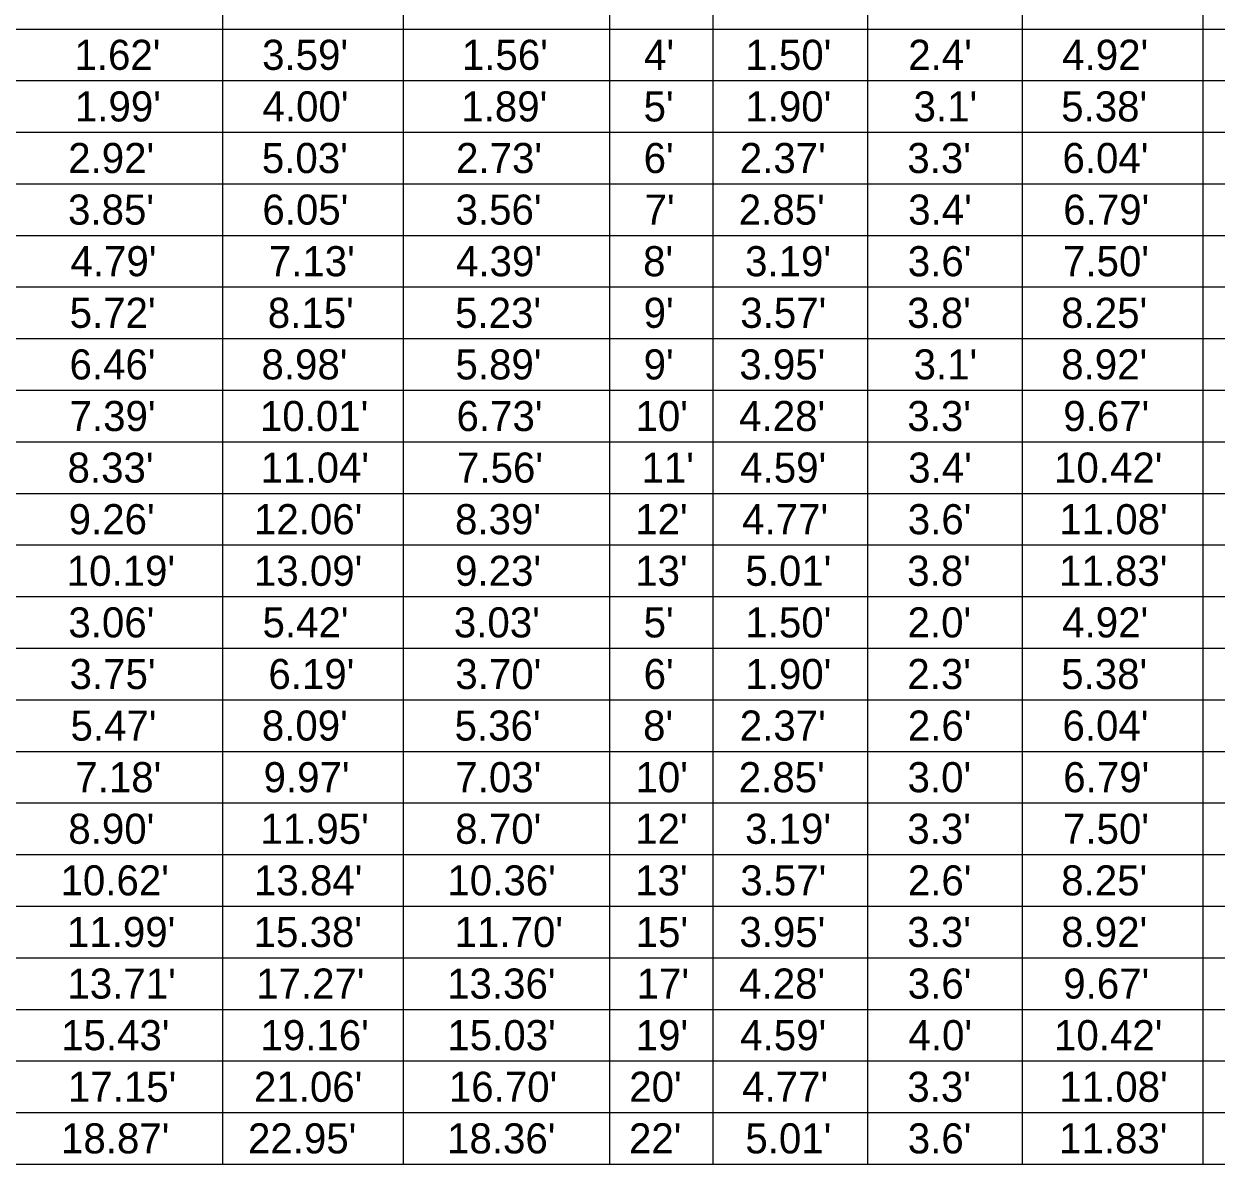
# Model space of a CAD drawing. Extents: x -1.3 to 14.6, y 0 to 8.4.
# Drawn here: x 4.058 to 6.831, y 2.19 to 4.842 of the extents above; entities that cross this region are included whole.
import ezdxf

# ---------------------------------------------------------------- set-up
doc = ezdxf.new("R2010")
doc.units = 0
doc.layers.add('Table', color=7, linetype='Continuous')

msp = doc.modelspace()

# ---------------------------------------------------------------- linework, layer by layer
at = {"layer": 'Table'}
for points in [[(4.52, 4.95), (4.52, 4.83), (4.52, 4.71), (4.52, 4.59), (4.52, 4.47), (4.52, 4.35), (4.52, 4.23), (4.52, 4.11), (4.52, 3.99), (4.52, 3.87), (4.52, 3.75), (4.52, 3.63), (4.52, 3.51), (4.52, 3.39), (4.52, 3.27), (4.52, 3.15), (4.52, 3.03), (4.52, 2.91), (4.52, 2.79), (4.52, 2.67), (4.52, 2.55), (4.52, 2.43), (4.52, 2.31), (4.52, 2.19)], [(4.94, 4.95), (4.94, 4.83), (4.94, 4.71), (4.94, 4.59), (4.94, 4.47), (4.94, 4.35), (4.94, 4.23), (4.94, 4.11), (4.94, 3.99), (4.94, 3.87), (4.94, 3.75), (4.94, 3.63), (4.94, 3.51), (4.94, 3.39), (4.94, 3.27), (4.94, 3.15), (4.94, 3.03), (4.94, 2.91), (4.94, 2.79), (4.94, 2.67), (4.94, 2.55), (4.94, 2.43), (4.94, 2.31), (4.94, 2.19)], [(5.42, 4.95), (5.42, 4.83), (5.42, 4.71), (5.42, 4.59), (5.42, 4.47), (5.42, 4.35), (5.42, 4.23), (5.42, 4.11), (5.42, 3.99), (5.42, 3.87), (5.42, 3.75), (5.42, 3.63), (5.42, 3.51), (5.42, 3.39), (5.42, 3.27), (5.42, 3.15), (5.42, 3.03), (5.42, 2.91), (5.42, 2.79), (5.42, 2.67), (5.42, 2.55), (5.42, 2.43), (5.42, 2.31), (5.42, 2.19)], [(5.66, 4.95), (5.66, 4.83), (5.66, 4.71), (5.66, 4.59), (5.66, 4.47), (5.66, 4.35), (5.66, 4.23), (5.66, 4.11), (5.66, 3.99), (5.66, 3.87), (5.66, 3.75), (5.66, 3.63), (5.66, 3.51), (5.66, 3.39), (5.66, 3.27), (5.66, 3.15), (5.66, 3.03), (5.66, 2.91), (5.66, 2.79), (5.66, 2.67), (5.66, 2.55), (5.66, 2.43), (5.66, 2.31), (5.66, 2.19)], [(6.02, 4.95), (6.02, 4.83), (6.02, 4.71), (6.02, 4.59), (6.02, 4.47), (6.02, 4.35), (6.02, 4.23), (6.02, 4.11), (6.02, 3.99), (6.02, 3.87), (6.02, 3.75), (6.02, 3.63), (6.02, 3.51), (6.02, 3.39), (6.02, 3.27), (6.02, 3.15), (6.02, 3.03), (6.02, 2.91), (6.02, 2.79), (6.02, 2.67), (6.02, 2.55), (6.02, 2.43), (6.02, 2.31), (6.02, 2.19)], [(6.38, 4.95), (6.38, 4.83), (6.38, 4.71), (6.38, 4.59), (6.38, 4.47), (6.38, 4.35), (6.38, 4.23), (6.38, 4.11), (6.38, 3.99), (6.38, 3.87), (6.38, 3.75), (6.38, 3.63), (6.38, 3.51), (6.38, 3.39), (6.38, 3.27), (6.38, 3.15), (6.38, 3.03), (6.38, 2.91), (6.38, 2.79), (6.38, 2.67), (6.38, 2.55), (6.38, 2.43), (6.38, 2.31), (6.38, 2.19)], [(6.8, 4.95), (6.8, 4.83), (6.8, 4.71), (6.8, 4.59), (6.8, 4.47), (6.8, 4.35), (6.8, 4.23), (6.8, 4.11), (6.8, 3.99), (6.8, 3.87), (6.8, 3.75), (6.8, 3.63), (6.8, 3.51), (6.8, 3.39), (6.8, 3.27), (6.8, 3.15), (6.8, 3.03), (6.8, 2.91), (6.8, 2.79), (6.8, 2.67), (6.8, 2.55), (6.8, 2.43), (6.8, 2.31), (6.8, 2.19)], [(4.04, 4.83), (4.52, 4.83), (4.94, 4.83), (5.42, 4.83), (5.66, 4.83), (6.02, 4.83), (6.38, 4.83), (6.8, 4.83), (7.22, 4.83), (7.64, 4.83), (8.06, 4.83), (8.42, 4.83), (8.84, 4.83), (9.26, 4.83), (9.68, 4.83), (10.1, 4.83), (10.52, 4.83), (10.94, 4.83), (11.36, 4.83), (11.78, 4.83), (12.2, 4.83), (12.62, 4.83), (13.04, 4.83), (13.46, 4.83)], [(4.04, 4.71), (4.52, 4.71), (4.94, 4.71), (5.42, 4.71), (5.66, 4.71), (6.02, 4.71), (6.38, 4.71), (6.8, 4.71), (7.22, 4.71), (7.64, 4.71), (8.06, 4.71), (8.42, 4.71), (8.84, 4.71), (9.26, 4.71), (9.68, 4.71), (10.1, 4.71), (10.52, 4.71), (10.94, 4.71), (11.36, 4.71), (11.78, 4.71), (12.2, 4.71), (12.62, 4.71), (13.04, 4.71), (13.46, 4.71)], [(4.04, 4.59), (4.52, 4.59), (4.94, 4.59), (5.42, 4.59), (5.66, 4.59), (6.02, 4.59), (6.38, 4.59), (6.8, 4.59), (7.22, 4.59), (7.64, 4.59), (8.06, 4.59), (8.42, 4.59), (8.84, 4.59), (9.26, 4.59), (9.68, 4.59), (10.1, 4.59), (10.52, 4.59), (10.94, 4.59), (11.36, 4.59), (11.78, 4.59), (12.2, 4.59), (12.62, 4.59), (13.04, 4.59), (13.46, 4.59)], [(4.04, 4.47), (4.52, 4.47), (4.94, 4.47), (5.42, 4.47), (5.66, 4.47), (6.02, 4.47), (6.38, 4.47), (6.8, 4.47), (7.22, 4.47), (7.64, 4.47), (8.06, 4.47), (8.42, 4.47), (8.84, 4.47), (9.26, 4.47), (9.68, 4.47), (10.1, 4.47), (10.52, 4.47), (10.94, 4.47), (11.36, 4.47), (11.78, 4.47), (12.2, 4.47), (12.62, 4.47), (13.04, 4.47), (13.46, 4.47)], [(4.04, 4.35), (4.52, 4.35), (4.94, 4.35), (5.42, 4.35), (5.66, 4.35), (6.02, 4.35), (6.38, 4.35), (6.8, 4.35), (7.22, 4.35), (7.64, 4.35), (8.06, 4.35), (8.42, 4.35), (8.84, 4.35), (9.26, 4.35), (9.68, 4.35), (10.1, 4.35), (10.52, 4.35), (10.94, 4.35), (11.36, 4.35), (11.78, 4.35), (12.2, 4.35), (12.62, 4.35), (13.04, 4.35), (13.46, 4.35)], [(4.04, 4.23), (4.52, 4.23), (4.94, 4.23), (5.42, 4.23), (5.66, 4.23), (6.02, 4.23), (6.38, 4.23), (6.8, 4.23), (7.22, 4.23), (7.64, 4.23), (8.06, 4.23), (8.42, 4.23), (8.84, 4.23), (9.26, 4.23), (9.68, 4.23), (10.1, 4.23), (10.52, 4.23), (10.94, 4.23), (11.36, 4.23), (11.78, 4.23), (12.2, 4.23), (12.62, 4.23), (13.04, 4.23), (13.46, 4.23)], [(4.04, 4.11), (4.52, 4.11), (4.94, 4.11), (5.42, 4.11), (5.66, 4.11), (6.02, 4.11), (6.38, 4.11), (6.8, 4.11), (7.22, 4.11), (7.64, 4.11), (8.06, 4.11), (8.42, 4.11), (8.84, 4.11), (9.26, 4.11), (9.68, 4.11), (10.1, 4.11), (10.52, 4.11), (10.94, 4.11), (11.36, 4.11), (11.78, 4.11), (12.2, 4.11), (12.62, 4.11), (13.04, 4.11), (13.46, 4.11)], [(4.04, 3.99), (4.52, 3.99), (4.94, 3.99), (5.42, 3.99), (5.66, 3.99), (6.02, 3.99), (6.38, 3.99), (6.8, 3.99), (7.22, 3.99), (7.64, 3.99), (8.06, 3.99), (8.42, 3.99), (8.84, 3.99), (9.26, 3.99), (9.68, 3.99), (10.1, 3.99), (10.52, 3.99), (10.94, 3.99), (11.36, 3.99), (11.78, 3.99), (12.2, 3.99), (12.62, 3.99), (13.04, 3.99), (13.46, 3.99)], [(4.04, 3.87), (4.52, 3.87), (4.94, 3.87), (5.42, 3.87), (5.66, 3.87), (6.02, 3.87), (6.38, 3.87), (6.8, 3.87), (7.22, 3.87), (7.64, 3.87), (8.06, 3.87), (8.42, 3.87), (8.84, 3.87), (9.26, 3.87), (9.68, 3.87), (10.1, 3.87), (10.52, 3.87), (10.94, 3.87), (11.36, 3.87), (11.78, 3.87), (12.2, 3.87), (12.62, 3.87), (13.04, 3.87), (13.46, 3.87)], [(4.04, 3.75), (4.52, 3.75), (4.94, 3.75), (5.42, 3.75), (5.66, 3.75), (6.02, 3.75), (6.38, 3.75), (6.8, 3.75), (7.22, 3.75), (7.64, 3.75), (8.06, 3.75), (8.42, 3.75), (8.84, 3.75), (9.26, 3.75), (9.68, 3.75), (10.1, 3.75), (10.52, 3.75), (10.94, 3.75), (11.36, 3.75), (11.78, 3.75), (12.2, 3.75), (12.62, 3.75), (13.04, 3.75), (13.46, 3.75)], [(4.04, 3.63), (4.52, 3.63), (4.94, 3.63), (5.42, 3.63), (5.66, 3.63), (6.02, 3.63), (6.38, 3.63), (6.8, 3.63), (7.22, 3.63), (7.64, 3.63), (8.06, 3.63), (8.42, 3.63), (8.84, 3.63), (9.26, 3.63), (9.68, 3.63), (10.1, 3.63), (10.52, 3.63), (10.94, 3.63), (11.36, 3.63), (11.78, 3.63), (12.2, 3.63), (12.62, 3.63), (13.04, 3.63), (13.46, 3.63)], [(4.04, 3.51), (4.52, 3.51), (4.94, 3.51), (5.42, 3.51), (5.66, 3.51), (6.02, 3.51), (6.38, 3.51), (6.8, 3.51), (7.22, 3.51), (7.64, 3.51), (8.06, 3.51), (8.42, 3.51), (8.84, 3.51), (9.26, 3.51), (9.68, 3.51), (10.1, 3.51), (10.52, 3.51), (10.94, 3.51), (11.36, 3.51), (11.78, 3.51), (12.2, 3.51), (12.62, 3.51), (13.04, 3.51), (13.46, 3.51)], [(4.04, 3.39), (4.52, 3.39), (4.94, 3.39), (5.42, 3.39), (5.66, 3.39), (6.02, 3.39), (6.38, 3.39), (6.8, 3.39), (7.22, 3.39), (7.64, 3.39), (8.06, 3.39), (8.42, 3.39), (8.84, 3.39), (9.26, 3.39), (9.68, 3.39), (10.1, 3.39), (10.52, 3.39), (10.94, 3.39), (11.36, 3.39), (11.78, 3.39), (12.2, 3.39), (12.62, 3.39), (13.04, 3.39), (13.46, 3.39)], [(4.04, 3.27), (4.52, 3.27), (4.94, 3.27), (5.42, 3.27), (5.66, 3.27), (6.02, 3.27), (6.38, 3.27), (6.8, 3.27), (7.22, 3.27), (7.64, 3.27), (8.06, 3.27), (8.42, 3.27), (8.84, 3.27), (9.26, 3.27), (9.68, 3.27), (10.1, 3.27), (10.52, 3.27), (10.94, 3.27), (11.36, 3.27), (11.78, 3.27), (12.2, 3.27), (12.62, 3.27), (13.04, 3.27), (13.46, 3.27)], [(4.04, 3.15), (4.52, 3.15), (4.94, 3.15), (5.42, 3.15), (5.66, 3.15), (6.02, 3.15), (6.38, 3.15), (6.8, 3.15), (7.22, 3.15), (7.64, 3.15), (8.06, 3.15), (8.42, 3.15), (8.84, 3.15), (9.26, 3.15), (9.68, 3.15), (10.1, 3.15), (10.52, 3.15), (10.94, 3.15), (11.36, 3.15), (11.78, 3.15), (12.2, 3.15), (12.62, 3.15), (13.04, 3.15), (13.46, 3.15)], [(4.04, 3.03), (4.52, 3.03), (4.94, 3.03), (5.42, 3.03), (5.66, 3.03), (6.02, 3.03), (6.38, 3.03), (6.8, 3.03), (7.22, 3.03), (7.64, 3.03), (8.06, 3.03), (8.42, 3.03), (8.84, 3.03), (9.26, 3.03), (9.68, 3.03), (10.1, 3.03), (10.52, 3.03), (10.94, 3.03), (11.36, 3.03), (11.78, 3.03), (12.2, 3.03), (12.62, 3.03), (13.04, 3.03), (13.46, 3.03)], [(4.04, 2.91), (4.52, 2.91), (4.94, 2.91), (5.42, 2.91), (5.66, 2.91), (6.02, 2.91), (6.38, 2.91), (6.8, 2.91), (7.22, 2.91), (7.64, 2.91), (8.06, 2.91), (8.42, 2.91), (8.84, 2.91), (9.26, 2.91), (9.68, 2.91), (10.1, 2.91), (10.52, 2.91), (10.94, 2.91), (11.36, 2.91), (11.78, 2.91), (12.2, 2.91), (12.62, 2.91), (13.04, 2.91), (13.46, 2.91)], [(4.04, 2.79), (4.52, 2.79), (4.94, 2.79), (5.42, 2.79), (5.66, 2.79), (6.02, 2.79), (6.38, 2.79), (6.8, 2.79), (7.22, 2.79), (7.64, 2.79), (8.06, 2.79), (8.42, 2.79), (8.84, 2.79), (9.26, 2.79), (9.68, 2.79), (10.1, 2.79), (10.52, 2.79), (10.94, 2.79), (11.36, 2.79), (11.78, 2.79), (12.2, 2.79), (12.62, 2.79), (13.04, 2.79), (13.46, 2.79)], [(4.04, 2.67), (4.52, 2.67), (4.94, 2.67), (5.42, 2.67), (5.66, 2.67), (6.02, 2.67), (6.38, 2.67), (6.8, 2.67), (7.22, 2.67), (7.64, 2.67), (8.06, 2.67), (8.42, 2.67), (8.84, 2.67), (9.26, 2.67), (9.68, 2.67), (10.1, 2.67), (10.52, 2.67), (10.94, 2.67), (11.36, 2.67), (11.78, 2.67), (12.2, 2.67), (12.62, 2.67), (13.04, 2.67), (13.46, 2.67)], [(4.04, 2.55), (4.52, 2.55), (4.94, 2.55), (5.42, 2.55), (5.66, 2.55), (6.02, 2.55), (6.38, 2.55), (6.8, 2.55), (7.22, 2.55), (7.64, 2.55), (8.06, 2.55), (8.42, 2.55), (8.84, 2.55), (9.26, 2.55), (9.68, 2.55), (10.1, 2.55), (10.52, 2.55), (10.94, 2.55), (11.36, 2.55), (11.78, 2.55), (12.2, 2.55), (12.62, 2.55), (13.04, 2.55), (13.46, 2.55)], [(4.04, 2.43), (4.52, 2.43), (4.94, 2.43), (5.42, 2.43), (5.66, 2.43), (6.02, 2.43), (6.38, 2.43), (6.8, 2.43), (7.22, 2.43), (7.64, 2.43), (8.06, 2.43), (8.42, 2.43), (8.84, 2.43), (9.26, 2.43), (9.68, 2.43), (10.1, 2.43), (10.52, 2.43), (10.94, 2.43), (11.36, 2.43), (11.78, 2.43), (12.2, 2.43), (12.62, 2.43), (13.04, 2.43), (13.46, 2.43)], [(4.04, 2.31), (4.52, 2.31), (4.94, 2.31), (5.42, 2.31), (5.66, 2.31), (6.02, 2.31), (6.38, 2.31), (6.8, 2.31), (7.22, 2.31), (7.64, 2.31), (8.06, 2.31), (8.42, 2.31), (8.84, 2.31), (9.26, 2.31), (9.68, 2.31), (10.1, 2.31), (10.52, 2.31), (10.94, 2.31), (11.36, 2.31), (11.78, 2.31), (12.2, 2.31), (12.62, 2.31), (13.04, 2.31), (13.46, 2.31)], [(4.04, 2.19), (4.52, 2.19), (4.94, 2.19), (5.42, 2.19), (5.66, 2.19), (6.02, 2.19), (6.38, 2.19), (6.8, 2.19), (7.22, 2.19), (7.64, 2.19), (8.06, 2.19), (8.42, 2.19), (8.84, 2.19), (9.26, 2.19), (9.68, 2.19), (10.1, 2.19), (10.52, 2.19), (10.94, 2.19), (11.36, 2.19), (11.78, 2.19), (12.2, 2.19), (12.62, 2.19), (13.04, 2.19), (13.46, 2.19)]]:
    msp.add_lwpolyline(points, dxfattribs=at)

# ---------------------------------------------------------------- texts
for s, p in [("1.62'", (4.1754, 4.735)), ("3.59'", (4.6119, 4.735)), ("1.56'", (5.0765, 4.735)), ("4'", (5.5003, 4.735)), ("1.50'", (5.7359, 4.735)), ("2.4'", (6.1148, 4.735)), ("4.92'", (6.4729, 4.735)), ("1.99'", (4.1765, 4.615)), ("4.00'", (4.6129, 4.615)), ("1.89'", (5.0752, 4.615)), ("5'", (5.4992, 4.615)), ("1.90'", (5.7359, 4.615)), ("3.1'", (6.1272, 4.615)), ("5.38'", (6.4705, 4.615)), ("2.92'", (4.1609, 4.495)), ("5.03'", (4.6113, 4.495)), ("2.73'", (5.063, 4.495)), ("6'", (5.4993, 4.495)), ("2.37'", (5.723, 4.495)), ("3.3'", (6.1126, 4.495)), ("6.04'", (6.4735, 4.495)), ("3.85'", (4.1605, 4.375)), ("6.05'", (4.6125, 4.375)), ("3.56'", (5.0619, 4.375)), ("7'", (5.5015, 4.375)), ("2.85'", (5.7206, 4.375)), ("3.4'", (6.1147, 4.375)), ("6.79'", (6.4753, 4.375)), ("4.79'", (4.1663, 4.255)), ("7.13'", (4.6275, 4.255)), ("4.39'", (5.0629, 4.255)), ("8'", (5.498, 4.255)), ("3.19'", (5.7353, 4.255)), ("3.6'", (6.1137, 4.255)), ("7.50'", (6.4747, 4.255)), ("5.72'", (4.1642, 4.135)), ("8.15'", (4.6251, 4.135)), ("5.23'", (5.0608, 4.135)), ("9'", (5.4993, 4.135)), ("3.57'", (5.7241, 4.135)), ("3.8'", (6.1124, 4.135)), ("8.25'", (6.4706, 4.135)), ("6.46'", (4.164, 4.015)), ("8.98'", (4.6104, 4.015)), ("5.89'", (5.0617, 4.015)), ("9'", (5.4993, 4.015)), ("3.95'", (5.7219, 4.015)), ("3.1'", (6.1272, 4.015)), ("8.92'", (6.4706, 4.015)), ("7.39'", (4.1641, 3.895)), ("10.01'", (4.6069, 3.895)), ("6.73'", (5.0641, 3.895)), ("10'", (5.4803, 3.895)), ("4.28'", (5.7216, 3.895)), ("3.3'", (6.1126, 3.895)), ("9.67'", (6.4753, 3.895)), ("8.33'", (4.1594, 3.775)), ("11.04'", (4.6085, 3.775)), ("7.56'", (5.0653, 3.775)), ("11'", (5.4943, 3.775)), ("4.59'", (5.724, 3.775)), ("3.4'", (6.1147, 3.775)), ("10.42'", (6.4539, 3.775)), ("9.26'", (4.162, 3.655)), ("12.06'", (4.593, 3.655)), ("8.39'", (5.0606, 3.655)), ("12'", (5.4797, 3.655)), ("4.77'", (5.7285, 3.655)), ("3.6'", (6.1137, 3.655)), ("11.08'", (6.4662, 3.655)), ("10.19'", (4.1575, 3.535)), ("13.09'", (4.5929, 3.535)), ("9.23'", (5.0608, 3.535)), ("13'", (5.4797, 3.535)), ("5.01'", (5.7359, 3.535)), ("3.8'", (6.1124, 3.535)), ("11.83'", (6.4656, 3.535)), ("3.06'", (4.1613, 3.415)), ("5.42'", (4.6129, 3.415)), (" 3.03'", (5.0319, 3.415)), ("5'", (5.4992, 3.415)), ("1.50'", (5.7359, 3.415)), ("2.0'", (6.1132, 3.415)), ("4.92'", (6.4729, 3.415)), ("3.75'", (4.1641, 3.295)), ("6.19'", (4.6265, 3.295)), (" 3.70'", (5.0353, 3.295)), ("6'", (5.4993, 3.295)), ("1.90'", (5.7359, 3.295)), ("2.3'", (6.1126, 3.295)), ("5.38'", (6.4705, 3.295)), ("5.47'", (4.1663, 3.175)), ("8.09'", (4.6112, 3.175)), (" 5.36'", (5.0336, 3.175)), ("8'", (5.498, 3.175)), ("2.37'", (5.723, 3.175)), ("2.6'", (6.1138, 3.175)), ("6.04'", (6.4735, 3.175)), ("7.18'", (4.1774, 3.055)), ("9.97'", (4.6153, 3.055)), (" 7.03'", (5.0353, 3.055)), ("10'", (5.4803, 3.055)), ("2.85'", (5.7206, 3.055)), ("3.0'", (6.1132, 3.055)), ("6.79'", (6.4753, 3.055)), ("8.90'", (4.1612, 2.935)), ("11.95'", (4.608, 2.935)), (" 8.70'", (5.0352, 2.935)), ("12'", (5.4797, 2.935)), ("3.19'", (5.7353, 2.935)), ("3.3'", (6.1126, 2.935)), ("7.50'", (6.4747, 2.935)), ("10.62'", (4.143, 2.815)), ("13.84'", (4.5931, 2.815)), ("10.36'", (5.0429, 2.815)), ("13'", (5.4797, 2.815)), ("3.57'", (5.7241, 2.815)), ("2.6'", (6.1138, 2.815)), ("8.25'", (6.4706, 2.815)), ("11.99'", (4.158, 2.695)), ("15.38'", (4.5921, 2.695)), ("11.70'", (5.0597, 2.695)), ("15'", (5.4808, 2.695)), ("3.95'", (5.7219, 2.695)), ("3.3'", (6.1126, 2.695)), ("8.92'", (6.4706, 2.695)), ("13.71'", (4.1591, 2.575)), ("17.27'", (4.598, 2.575)), ("13.36'", (5.0423, 2.575)), ("17'", (5.4831, 2.575)), ("4.28'", (5.7216, 2.575)), ("3.6'", (6.1137, 2.575)), ("9.67'", (6.4753, 2.575)), ("15.43'", (4.1444, 2.455)), ("19.16'", (4.608, 2.455)), ("15.03'", (5.0428, 2.455)), ("19'", (5.4808, 2.455)), ("4.59'", (5.724, 2.455)), ("4.0'", (6.1153, 2.455)), ("10.42'", (6.4539, 2.455)), ("17.15'", (4.1603, 2.335)), ("21.06'", (4.593, 2.335)), ("16.70'", (5.0463, 2.335)), ("20'", (5.4658, 2.335)), ("4.77'", (5.7285, 2.335)), ("3.3'", (6.1126, 2.335)), ("11.08'", (6.4662, 2.335)), ("18.87'", (4.1442, 2.215)), ("22.95'", (4.579, 2.215)), ("18.36'", (5.0421, 2.215)), ("22'", (5.4652, 2.215)), ("5.01'", (5.7359, 2.215)), ("3.6'", (6.1137, 2.215)), ("11.83'", (6.4656, 2.215))]:
    msp.add_text(s, height=0.07, rotation=0, dxfattribs=at).set_placement(p)

doc.saveas('drawing.dxf')
